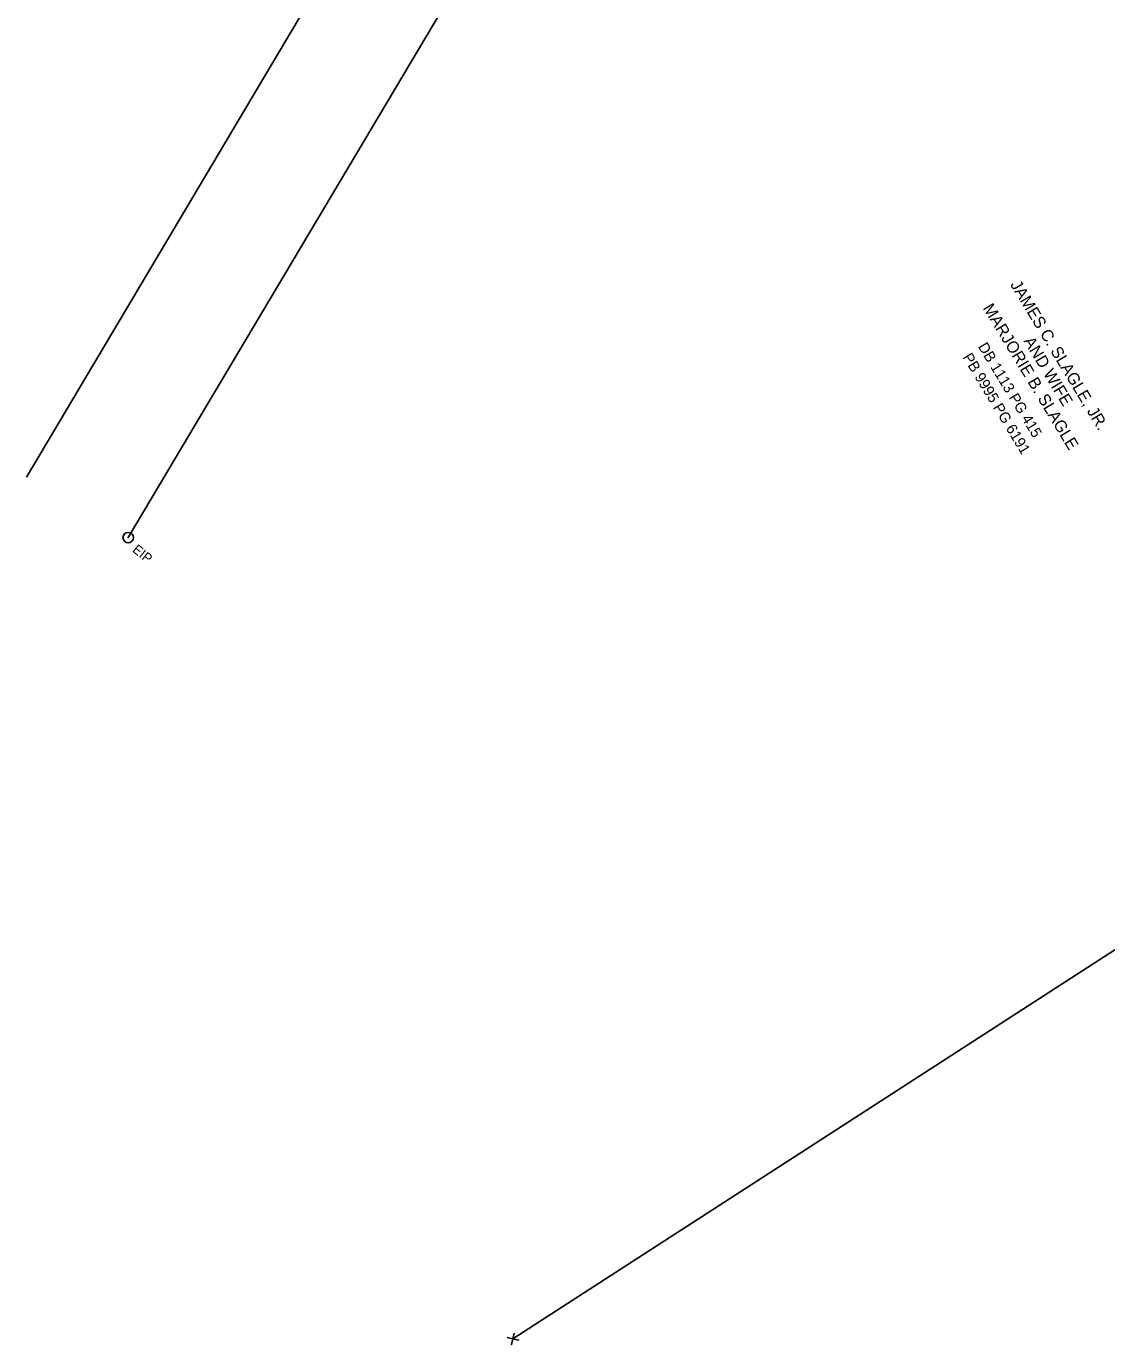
# Model space of a CAD drawing. Extents: x 1498375 to 1499839, y 700490 to 702854.
# Drawn here: x 1498425 to 1498880, y 701468 to 702024 of the extents above; entities that cross this region are included whole.
import ezdxf

# ---------------------------------------------------------------- set-up
doc = ezdxf.new("R2010")
doc.units = 0
for name, color, linetype in [('Exist Horizontal Alignment', 7, 'Continuous'), ('Exist Property Corner CELL', 7, 'Continuous'), ('Exist Property Deed Book Text', 7, 'Continuous'), ('Exist Property Iron Pin CELL', 7, 'Continuous'), ('Exist Property Iron Pin Text', 7, 'Continuous'), ('Exist Property Line', 7, 'Continuous'), ('Exist Property Owner Text', 7, 'Continuous'), ('Exist Right of Way Easement Line', 7, 'Continuous'), ('Exist Right of Way Line', 7, 'Continuous'), ('Exist Roads EOP', 7, 'Continuous'), ('Exist Utilities Telephone UG Cable', 7, 'Continuous')]:
    doc.layers.add(name, color=color, linetype=linetype)

# ---------------------------------------------------------------- blocks, each defined once
blk = doc.blocks.new('EXIST PROPERTY IRON PIN')
at = {"layer": 'Exist Property Iron Pin CELL'}
for radius in [0.0441, 0.00141]:
    blk.add_circle((0, 0), radius, dxfattribs=at)

msp = doc.modelspace()

# ---------------------------------------------------------------- linework, layer by layer
at = {"layer": 'Exist Horizontal Alignment'}
msp.add_arc((1497414.63, 701128.78), 1850, 28.43684, 41.64975, dxfattribs=at)
at = {"layer": 'Exist Property Corner CELL'}
msp.add_line((1498629.83, 701470.25), (1498629.83, 701470.25), dxfattribs=at)
msp.add_lwpolyline([(1498630.36, 701472.7), (1498629.31, 701467.81), (1498629.83, 701470.25), (1498632.27, 701469.73), (1498627.39, 701470.78)], dxfattribs=at)
at = {"layer": 'Exist Property Line'}
for p, q in [((1498467.5, 701808.33), (1498779.43, 702332.92)), ((1499031.38, 701729.82), (1498629.83, 701470.25))]:
    msp.add_line(p, q, dxfattribs=at)
at = {"layer": 'Exist Right of Way Easement Line'}
msp.add_line((1498744.54, 702372.08), (1498424.52, 701833.88), dxfattribs=at)
at = {"layer": 'Exist Right of Way Line'}
msp.add_arc((1497414.24, 701128.85), 1820.32, 28.42903, 41.4116, dxfattribs=at)
at = {"layer": 'Exist Roads EOP'}
for points in [[(1499091.1, 701936.52), (1499070.56, 701974.83), (1499049.05, 702015.25), (1499026.27, 702055.91), (1499004.38, 702092.76), (1498980.68, 702131.19), (1498955.1, 702169.98), (1498929.13, 702206.36), (1498901.23, 702244.8), (1498872.92, 702280.9), (1498841.61, 702319.53), (1498811.71, 702353.95), (1498782.02, 702388.2)], [(1499076.04, 701928.59), (1499055.35, 701966.79), (1499033.8, 702006.23), (1499010.35, 702048.03), (1498989.2, 702083.56), (1498965.39, 702121.96), (1498940.2, 702160.05), (1498914.57, 702197.35), (1498887.05, 702234.06), (1498859.77, 702269.48), (1498828.57, 702307.58), (1498798.2, 702342.6), (1498769.18, 702377.27)]]:
    msp.add_spline(points, degree=3, dxfattribs=at)
at = {"layer": 'Exist Utilities Telephone UG Cable'}
msp.add_spline([(1498782.77, 702388.86), (1498812.47, 702354.61), (1498842.38, 702320.17), (1498873.7, 702281.52), (1498902.03, 702245.4), (1498929.94, 702206.94), (1498955.92, 702170.54), (1498981.52, 702131.72), (1499005.24, 702093.28), (1499027.14, 702056.41), (1499049.93, 702015.73), (1499071.44, 701975.3), (1499091.98, 701936.99)], degree=3, dxfattribs=at)

# ---------------------------------------------------------------- block references
at = {"layer": 'Exist Property Iron Pin CELL', "xscale": 50, "yscale": 50}
msp.add_blockref('EXIST PROPERTY IRON PIN', (1498467.5, 701808.33), dxfattribs=at)

# ---------------------------------------------------------------- texts
at = {"layer": 'Exist Property Deed Book Text'}
for s, p in [('DB 1113 PG 415', (1498825.95, 701888.94)), ('PB 9995 PG 6191', (1498819.49, 701884.48))]:
    msp.add_text(s, height=4.5, rotation=301.2023, dxfattribs=at).set_placement(p)
at = {"layer": 'Exist Property Iron Pin Text'}
msp.add_text('EIP', height=4, rotation=320.8703, dxfattribs=at).set_placement((1498468.96, 701802.64))
at = {"layer": 'Exist Property Owner Text'}
for s, p in [('JAMES C. SLAGLE, JR.', (1498839.56, 701915.07)), ('MARJORIE B. SLAGLE', (1498828.01, 701905.2)), ('AND WIFE', (1498845.21, 701891.27))]:
    msp.add_text(s, height=5, rotation=301.2023, dxfattribs=at).set_placement(p)

doc.saveas('drawing.dxf')
